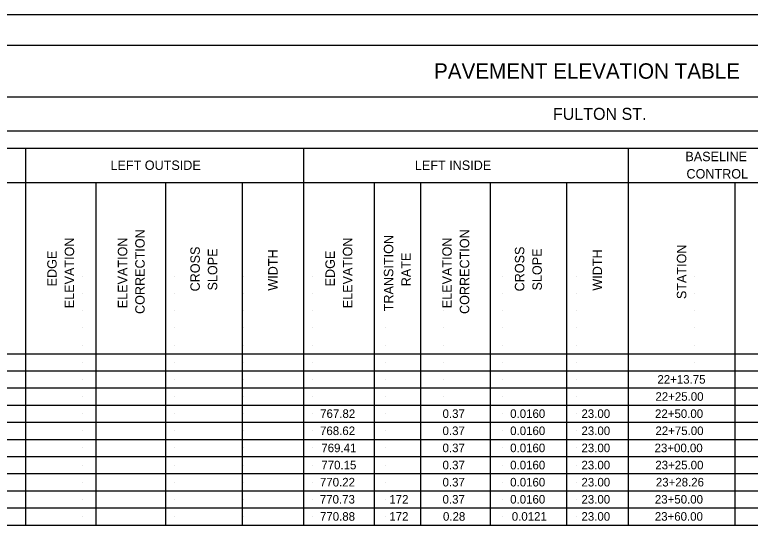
# Model space of a CAD drawing. Extents: x -15.4 to 18.6, y -12.6 to 9.4.
# Drawn here: x -8.3 to 3.72, y 0.98 to 9.39 of the extents above; entities that cross this region are included whole.
import ezdxf

# ---------------------------------------------------------------- set-up
doc = ezdxf.new("R2010")
doc.units = 0
for name, color, linetype in [('SH_Border', 7, 'Continuous'), ('SH_Cut_Line', 7, 'Continuous'), ('SH_Data', 7, 'Continuous'), ('SH_Text', 7, 'Continuous')]:
    doc.layers.add(name, color=color, linetype=linetype)

msp = doc.modelspace()

# ---------------------------------------------------------------- linework, layer by layer
at = {"layer": 'SH_Border'}
msp.add_lwpolyline([(-13.357, 8.888), (18.143, 8.888), (18.143, -12.112), (-13.357, -12.112)], close=True, dxfattribs=at)
at = {"layer": 'SH_Cut_Line'}
msp.add_lwpolyline([(-15.357, -12.612), (18.643, -12.612), (18.643, 9.388), (-15.357, 9.388)], close=True, dxfattribs=at)
at = {"layer": 'SH_Data'}
for p, q in [((-12.667, 8.888), (15.877, 8.888)), ((-11.514, 8.048), (13.999, 8.048)), ((-11.514, 7.488), (13.999, 7.488)), ((-12.667, 7.208), (15.877, 7.208)), ((-8.121, 7.208), (-8.121, 1.048)), ((-3.575, 7.208), (-3.575, 1.048)), ((1.729, 7.208), (1.729, 1.048)), ((-12.667, 6.648), (14.576, 6.648)), ((-6.968, 6.648), (-6.968, 1.048)), ((-5.831, 6.648), (-5.831, 1.048)), ((-4.58, 6.648), (-4.58, 1.048)), ((-2.422, 6.648), (-2.422, 1.048)), ((-1.664, 6.648), (-1.664, 1.048)), ((-0.528, 6.648), (-0.528, 1.048)), ((0.724, 6.648), (0.724, 1.048)), ((3.474, 6.648), (3.474, 1.048)), ((-7.182, 5.108), (-7.182, 5.108)), ((-5.682, 5.108), (-5.682, 5.108)), ((-4.557, 5.108), (-4.557, 5.108)), ((-3.432, 5.108), (-3.432, 5.108)), ((-2.232, 5.108), (-2.232, 5.108)), ((-1.282, 5.108), (-1.282, 5.108)), ((-0.332, 5.108), (-0.332, 5.108)), ((0.893, 5.108), (0.893, 5.108)), ((2.818, 5.108), (2.818, 5.108)), ((-7.182, 4.828), (-7.182, 4.828)), ((-5.682, 4.828), (-5.682, 4.828)), ((-4.557, 4.828), (-4.557, 4.828)), ((-3.432, 4.828), (-3.432, 4.828)), ((-2.232, 4.828), (-2.232, 4.828)), ((-1.282, 4.828), (-1.282, 4.828)), ((-0.332, 4.828), (-0.332, 4.828)), ((0.893, 4.828), (0.893, 4.828)), ((2.818, 4.828), (2.818, 4.828)), ((-7.182, 4.548), (-7.182, 4.548)), ((-5.682, 4.548), (-5.682, 4.548)), ((-4.557, 4.548), (-4.557, 4.548)), ((-3.432, 4.548), (-3.432, 4.548)), ((-2.232, 4.548), (-2.232, 4.548)), ((-1.282, 4.548), (-1.282, 4.548)), ((-0.332, 4.548), (-0.332, 4.548)), ((0.893, 4.548), (0.893, 4.548)), ((2.818, 4.548), (2.818, 4.548)), ((-7.182, 4.268), (-7.182, 4.268)), ((-5.682, 4.268), (-5.682, 4.268)), ((-4.557, 4.268), (-4.557, 4.268)), ((-3.432, 4.268), (-3.432, 4.268)), ((-2.232, 4.268), (-2.232, 4.268)), ((-1.282, 4.268), (-1.282, 4.268)), ((-0.332, 4.268), (-0.332, 4.268)), ((0.893, 4.268), (0.893, 4.268)), ((2.818, 4.268), (2.818, 4.268)), ((-7.182, 3.988), (-7.182, 3.988)), ((-5.682, 3.988), (-5.682, 3.988)), ((-4.557, 3.988), (-4.557, 3.988)), ((-3.432, 3.988), (-3.432, 3.988)), ((-2.232, 3.988), (-2.232, 3.988)), ((-1.282, 3.988), (-1.282, 3.988)), ((-0.332, 3.988), (-0.332, 3.988)), ((0.893, 3.988), (0.893, 3.988)), ((2.818, 3.988), (2.818, 3.988)), ((-12.667, 3.848), (15.877, 3.848)), ((-7.182, 3.708), (-7.182, 3.708)), ((-5.682, 3.708), (-5.682, 3.708)), ((-4.557, 3.708), (-4.557, 3.708)), ((-3.432, 3.708), (-3.432, 3.708)), ((-2.232, 3.708), (-2.232, 3.708)), ((-1.282, 3.708), (-1.282, 3.708)), ((-0.332, 3.708), (-0.332, 3.708)), ((0.893, 3.708), (0.893, 3.708)), ((2.818, 3.708), (2.818, 3.708)), ((-12.667, 3.568), (15.877, 3.568)), ((-7.182, 3.428), (-7.182, 3.428)), ((-5.682, 3.428), (-5.682, 3.428)), ((-4.557, 3.428), (-4.557, 3.428)), ((-3.432, 3.428), (-3.432, 3.428)), ((-2.232, 3.428), (-2.232, 3.428)), ((-1.282, 3.428), (-1.282, 3.428)), ((-0.332, 3.428), (-0.332, 3.428)), ((0.893, 3.428), (0.893, 3.428)), ((2.818, 3.428), (2.818, 3.428)), ((-12.667, 3.288), (15.877, 3.288)), ((-7.182, 3.148), (-7.182, 3.148)), ((-5.682, 3.148), (-5.682, 3.148)), ((-4.557, 3.148), (-4.557, 3.148)), ((-3.432, 3.148), (-3.432, 3.148)), ((-2.232, 3.148), (-2.232, 3.148)), ((-1.282, 3.148), (-1.282, 3.148)), ((-0.332, 3.148), (-0.332, 3.148)), ((0.893, 3.148), (0.893, 3.148)), ((2.818, 3.148), (2.818, 3.148)), ((-12.667, 3.008), (15.877, 3.008)), ((-7.182, 2.868), (-7.182, 2.868)), ((-5.682, 2.868), (-5.682, 2.868)), ((-4.557, 2.868), (-4.557, 2.868)), ((-3.432, 2.868), (-3.432, 2.868)), ((-2.232, 2.868), (-2.232, 2.868)), ((-1.282, 2.868), (-1.282, 2.868)), ((-0.332, 2.868), (-0.332, 2.868)), ((0.893, 2.868), (0.893, 2.868)), ((2.818, 2.868), (2.818, 2.868)), ((-12.667, 2.728), (15.877, 2.728)), ((-7.182, 2.588), (-7.182, 2.588)), ((-5.682, 2.588), (-5.682, 2.588)), ((-4.557, 2.588), (-4.557, 2.588)), ((-3.432, 2.588), (-3.432, 2.588)), ((-2.232, 2.588), (-2.232, 2.588)), ((-1.282, 2.588), (-1.282, 2.588)), ((-0.332, 2.588), (-0.332, 2.588)), ((0.893, 2.588), (0.893, 2.588)), ((2.818, 2.588), (2.818, 2.588)), ((-12.667, 2.448), (15.877, 2.448)), ((-7.182, 2.308), (-7.182, 2.308)), ((-5.682, 2.308), (-5.682, 2.308)), ((-4.557, 2.308), (-4.557, 2.308)), ((-3.432, 2.308), (-3.432, 2.308)), ((-2.232, 2.308), (-2.232, 2.308)), ((-1.282, 2.308), (-1.282, 2.308)), ((-0.332, 2.308), (-0.332, 2.308)), ((0.893, 2.308), (0.893, 2.308)), ((2.818, 2.308), (2.818, 2.308)), ((-12.667, 2.168), (15.877, 2.168)), ((-7.182, 2.028), (-7.182, 2.028)), ((-5.682, 2.028), (-5.682, 2.028)), ((-4.557, 2.028), (-4.557, 2.028)), ((-3.432, 2.028), (-3.432, 2.028)), ((-2.232, 2.028), (-2.232, 2.028)), ((-1.282, 2.028), (-1.282, 2.028)), ((-0.332, 2.028), (-0.332, 2.028)), ((0.893, 2.028), (0.893, 2.028)), ((2.818, 2.028), (2.818, 2.028)), ((-12.667, 1.888), (15.877, 1.888)), ((-7.182, 1.748), (-7.182, 1.748)), ((-7.182, 1.748), (-7.182, 1.748)), ((-5.682, 1.748), (-5.682, 1.748)), ((-5.682, 1.748), (-5.682, 1.748)), ((-4.557, 1.748), (-4.557, 1.748)), ((-3.432, 1.748), (-3.432, 1.748)), ((-2.232, 1.748), (-2.232, 1.748)), ((-1.282, 1.748), (-1.282, 1.748)), ((-0.332, 1.748), (-0.332, 1.748)), ((0.893, 1.748), (0.893, 1.748)), ((2.818, 1.748), (2.818, 1.748)), ((-12.667, 1.608), (15.877, 1.608)), ((-7.182, 1.468), (-7.182, 1.468)), ((-7.182, 1.468), (-7.182, 1.468)), ((-5.682, 1.468), (-5.682, 1.468)), ((-5.682, 1.468), (-5.682, 1.468)), ((-4.557, 1.468), (-4.557, 1.468)), ((-3.432, 1.468), (-3.432, 1.468)), ((-2.232, 1.468), (-2.232, 1.468)), ((-1.282, 1.468), (-1.282, 1.468)), ((-0.332, 1.468), (-0.332, 1.468)), ((0.893, 1.468), (0.893, 1.468)), ((2.818, 1.468), (2.818, 1.468)), ((-12.667, 1.328), (15.877, 1.328)), ((-7.185, 1.188), (-7.185, 1.188)), ((-7.185, 1.188), (-7.185, 1.188)), ((-7.182, 1.188), (-7.182, 1.188)), ((-5.685, 1.188), (-5.685, 1.188)), ((-5.685, 1.188), (-5.685, 1.188)), ((-5.682, 1.188), (-5.682, 1.188)), ((-4.557, 1.188), (-4.557, 1.188)), ((-3.432, 1.188), (-3.432, 1.188)), ((-2.232, 1.188), (-2.232, 1.188)), ((-1.282, 1.188), (-1.282, 1.188)), ((-0.332, 1.188), (-0.332, 1.188)), ((0.893, 1.188), (0.893, 1.188)), ((2.818, 1.188), (2.818, 1.188)), ((-12.667, 1.048), (15.877, 1.048))]:
    msp.add_line(p, q, dxfattribs=at)

# ---------------------------------------------------------------- texts
at = {"layer": 'SH_Text'}
for s, height, p in [('PAVEMENT ELEVATION TABLE', 0.252, (-1.443, 8.342)), ('FULTON ST.', 0.196, (0.5, 7.67)), ('BASELINE', 0.154, (2.664, 6.994)), ('LEFT OUTSIDE', 0.154, (-6.731, 6.851)), ('LEFT INSIDE ', 0.154, (-1.756, 6.851)), ('CONTROL', 0.154, (2.682, 6.711)), ('22+13.75', 0.14, (2.207, 3.358)), ('22+25.00', 0.14, (2.175, 3.078)), ('767.82', 0.14, (-3.304, 2.798)), ('0.37', 0.14, (-1.304, 2.798)), ('0.0160', 0.14, (-0.199, 2.798)), ('23.00', 0.14, (0.966, 2.798)), ('22+50.00', 0.14, (2.168, 2.798)), ('768.62', 0.14, (-3.306, 2.518)), ('0.37', 0.14, (-1.304, 2.518)), ('0.0160', 0.14, (-0.199, 2.518)), ('23.00', 0.14, (0.966, 2.518)), ('22+75.00', 0.14, (2.175, 2.518)), ('769.41', 0.14, (-3.285, 2.238)), ('0.37', 0.14, (-1.304, 2.238)), ('0.0160', 0.14, (-0.199, 2.238)), ('23.00', 0.14, (0.966, 2.238)), ('23+00.00', 0.14, (2.161, 2.238)), ('770.15', 0.14, (-3.285, 1.958)), ('0.37', 0.14, (-1.304, 1.958)), ('0.0160', 0.14, (-0.199, 1.958)), ('23.00', 0.14, (0.966, 1.958)), ('23+25.00', 0.14, (2.173, 1.958)), ('770.22', 0.14, (-3.308, 1.678)), ('0.37', 0.14, (-1.304, 1.678)), ('0.0160', 0.14, (-0.199, 1.678)), ('23.00', 0.14, (0.966, 1.678)), ('23+28.26', 0.14, (2.182, 1.678)), ('770.73', 0.14, (-3.309, 1.398)), ('172', 0.14, (-2.174, 1.398)), ('0.37', 0.14, (-1.304, 1.398)), ('0.0160', 0.14, (-0.199, 1.398)), ('23.00', 0.14, (0.966, 1.398)), ('23+50.00', 0.14, (2.166, 1.398)), ('770.88', 0.14, (-3.307, 1.118)), ('172', 0.14, (-2.174, 1.118)), ('0.28', 0.14, (-1.297, 1.118)), ('0.0121', 0.14, (-0.173, 1.118)), ('23.00', 0.14, (0.966, 1.118)), ('23+60.00', 0.14, (2.165, 1.118))]:
    msp.add_text(s, height=height, dxfattribs=at).set_placement(p)
for s, p in [('CORRECTION', (-6.172, 4.497)), ('TRANSITION', (-2.109, 4.541)), ('CORRECTION', (-0.868, 4.497)), ('ELEVATION', (-7.325, 4.591)), ('ELEVATION', (-6.457, 4.591)), ('ELEVATION', (-2.779, 4.591)), ('ELEVATION', (-1.154, 4.591)), ('CROSS', (-5.271, 4.866)), ('SLOPE', (-4.986, 4.881)), ('WIDTH', (-4, 4.878)), ('CROSS', (0.032, 4.866)), ('SLOPE', (0.318, 4.881)), ('WIDTH', (1.303, 4.878)), ('STATION', (2.679, 4.74)), ('EDGE', (-7.61, 4.948)), ('EDGE', (-3.064, 4.948)), ('RATE', (-1.823, 4.95))]:
    msp.add_text(s, height=0.154, rotation=90, dxfattribs=at).set_placement(p)

doc.saveas('drawing.dxf')
